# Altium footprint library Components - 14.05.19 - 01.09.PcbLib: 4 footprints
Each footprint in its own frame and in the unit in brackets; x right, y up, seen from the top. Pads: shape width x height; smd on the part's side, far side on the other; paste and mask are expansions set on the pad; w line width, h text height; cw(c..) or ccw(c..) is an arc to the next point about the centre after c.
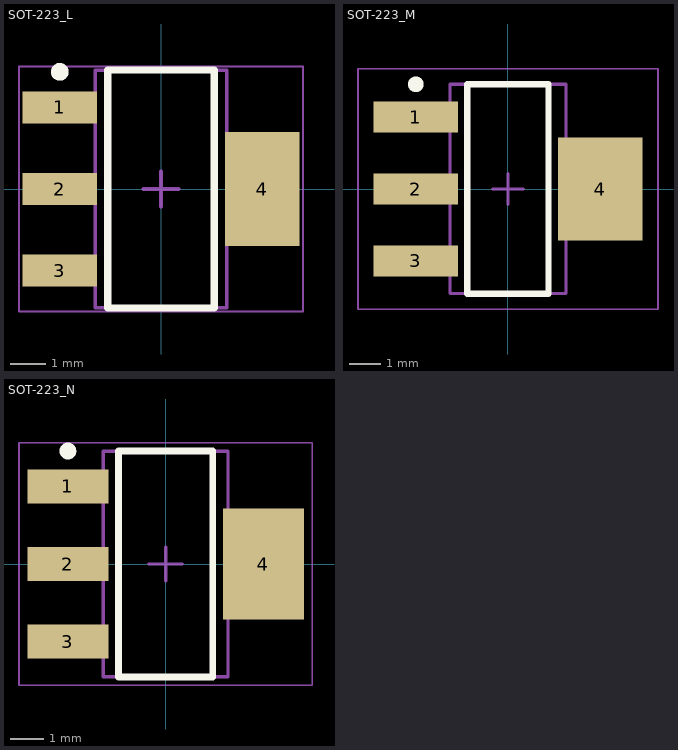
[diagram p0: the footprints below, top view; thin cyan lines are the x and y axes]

## PCBComponent_1 [mm]

## SOT-223_L [mm] "SOT223, 4-Leads, Body 6.5x3.5mm, Pitch 2.3mm, Lead Span 7mm, IPC High Density"
height 1.8
pads (4):
  rect 2.1x0.9 smd: 1(-2.85,2.3) 2(-2.85,0) 3(-2.85,-2.3)
  rect 2.1x3.2 smd: 4(2.85,0)
Top Overlay:
  circle w0.25: c-2.85,3.3 r0.125
  lines w0.2: -1.5,-3.35 1.5,-3.35 1.5,3.35 -1.5,3.35 -1.5,-3.35
Mechanical 13:
  lines w0.1: -1.85,-3.35 1.85,-3.35 1.85,3.35 -1.85,3.35 -1.85,-3.35
Mechanical 15:
  lines w0.05: -4,-3.45 4,-3.45 4,3.45 -4,3.45 -4,-3.45
  lines w0.1: -0.5,0 0.5,0 ; 0,-0.5 0,0.5
3D body: height 1.8, standoff 0.02, extent -1.85,-3.35 1.85,3.35

## SOT-223_M [mm] "SOT223, 4-Leads, Body 6.5x3.5mm, Pitch 2.3mm, Lead Span 7mm, IPC Low Density"
height 1.8
pads (4):
  rect 2.7x1 smd: 1(-2.95,2.3) 2(-2.95,0) 3(-2.95,-2.3)
  rect 2.7x3.3 smd: 4(2.95,0)
Top Overlay:
  circle w0.25: c-2.95,3.35 r0.125
  lines w0.2: -1.3,-3.35 1.3,-3.35 1.3,3.35 -1.3,3.35 -1.3,-3.35
Mechanical 13:
  lines w0.1: -1.85,-3.35 1.85,-3.35 1.85,3.35 -1.85,3.35 -1.85,-3.35
Mechanical 15:
  lines w0.05: -4.8,-3.85 4.8,-3.85 4.8,3.85 -4.8,3.85 -4.8,-3.85
  lines w0.1: -0.5,0 0.5,0 ; 0,-0.5 0,0.5
3D body: height 1.8, standoff 0.02, extent -1.85,-3.35 1.85,3.35

## SOT-223_N [mm] "SOT223, 4-Leads, Body 6.5x3.5mm, Pitch 2.3mm, Lead Span 7mm, IPC Medium Density"
height 1.8
pads (4):
  rect 2.4x1 smd: 1(-2.9,2.3) 2(-2.9,0) 3(-2.9,-2.3)
  rect 2.4x3.3 smd: 4(2.9,0)
Top Overlay:
  circle w0.25: c-2.9,3.35 r0.125
  lines w0.2: -1.4,-3.35 1.4,-3.35 1.4,3.35 -1.4,3.35 -1.4,-3.35
Mechanical 13:
  lines w0.1: -1.85,-3.35 1.85,-3.35 1.85,3.35 -1.85,3.35 -1.85,-3.35
Mechanical 15:
  lines w0.05: -4.35,-3.6 4.35,-3.6 4.35,3.6 -4.35,3.6 -4.35,-3.6
  lines w0.1: -0.5,0 0.5,0 ; 0,-0.5 0,0.5
3D body: height 1.8, standoff 0.02, extent -1.85,-3.35 1.85,3.35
